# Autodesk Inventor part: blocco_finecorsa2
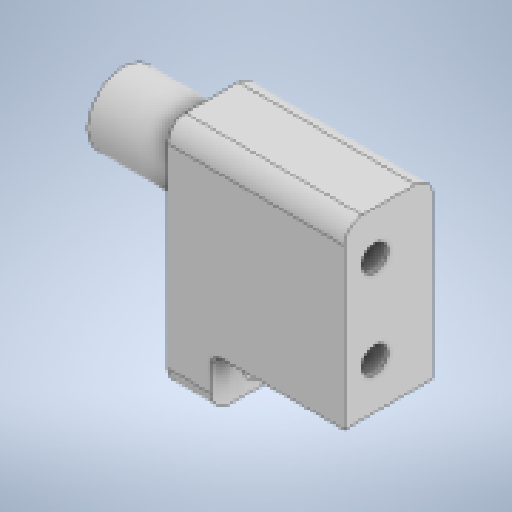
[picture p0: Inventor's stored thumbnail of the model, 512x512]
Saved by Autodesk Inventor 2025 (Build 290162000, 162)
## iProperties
Created: 2026-03
Part Number: blocco_finecorsa2
Material: Generico
Document SubType Name: Modeling
Designer: Ryzen5700u
Density: 1 g/cm^3
Appearance: Default
Author: Ryzen5700u
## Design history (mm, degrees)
sketch "Schizzo1"
  geometry: L1 (10, 5)-(-10, 5); L2 (-10, 5)-(-10, -5); L3 (-10, -5)-(10, -5); L4 (10, -5)-(10, 5); L5 (10, 5)-(-10, -5); L6 (-10, 5)-(10, -5); 1 further point
  constraints: 12 end point, 2 midpoint, 2 parallel, 1 horizontal, 1 perpendicular
  dimensions: "d0" = 20 distance of L3.end L2.end; "d1" = 10 distance of L2.end L1.end
extrude "Estrusione1" new body sketch "Schizzo1" distance "d2" = 22; taper "d3" = 0 deg
sketch "Schizzo2"
  geometry: C1 r 4 at (0, 4); 1 further point
  constraints: 1 centre point
  dimensions: "d4" = 8 diameter of C1; "d5" = 4 distance of point (0, 0) C1.centre
extrude "Estrusione2" join sketch "Schizzo2" distance "d6" = 10; taper "d7" = 0 deg
sketch "Schizzo3"
  geometry: C1 r 1.25 at (-1.6, 5.125) reference; C2 r 1.25 at (-1.6, -4.875) reference; 1 further point
hole "Foro1" sketch "Schizzo3" at (-1.6, 5.125), (-1.6, -4.875) diameter "d9" = 2.9; stored, may be unused: countersink angle "d13" = 90 deg, drill point angle "d15" = 118 deg; dims "d10" = 6, "d11" = 5.5, "d12" = 2.9, "d14" = 8
sketch "Schizzo4"
  geometry: L1 (5, -10)-(-5, -10) reference; L2 (5, 10)-(5, -10) reference; L3 (-5, 10)-(5, 10) reference; L4 (-5, -10)-(-5, 10) reference; L5 (5, -10)-(-5, -10) reference; L6 (5, -10)-(-5, -10); L7 (-5, -10)-(-5, -16); L8 (-5, -16)-(5, -16); L9 (5, -16)-(5, -10); C1 r 4 at (0, 4) reference; 2 further points
  constraints: 8 end point, 2 parallel, 1 horizontal, 1 perpendicular
  dimensions: "d16" = 6 distance of L7.end L6.end
extrude "Estrusione3" join sketch "Schizzo4" distance "d17" = 5; taper "d18" = 0 deg
fillet "Raccordo2" dims "d19" = 1
sketch "Schizzo5"
  geometry: L1 (-5, -16)-(5, -16) reference; 2 further points
  dimensions: "d27" = 2.5 distance from line of L1 point (0, -13.5)
hole "Foro2" sketch "Schizzo5" at (0, -13.5) diameter "d20" = 2.9; stored, may be unused: countersink angle "d24" = 90 deg, drill point angle "d26" = 118 deg; dims "d21" = 6, "d22" = 4, "d23" = 2, "d25" = 8
fillet "Raccordo3" dims "d28" = 2
node "Solido1"
node "Riferimento1"
node "Riferimento2"
node "Linea chiusa proiettata1"
